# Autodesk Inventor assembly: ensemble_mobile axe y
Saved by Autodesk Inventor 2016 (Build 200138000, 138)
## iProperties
Created: 2013-08
Part Number: ensemble_mobile axe y
Document SubType Name: Assembly
Designer: hilarion
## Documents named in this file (1)
- S:\TSTI2D\Documents en consultation\etude de cas 1  webcam\Webcam motorisee\ensemble_mobile axe y.iam
